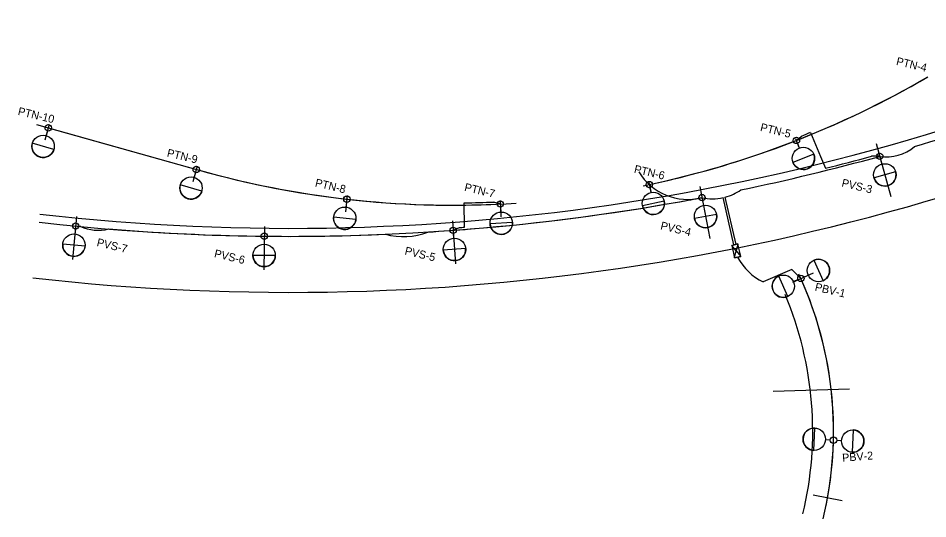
# Model space of a CAD drawing. Extents: x 0 to 511877, y 0 to 6211921.
# Drawn here: x 511512.3 to 511654.3, y 6211732.8 to 6211811 of the extents above; entities that cross this region are included whole.
import ezdxf

# ---------------------------------------------------------------- set-up
doc = ezdxf.new("R2010")
doc.units = 0
for name, color, linetype in [('Help', 7, 'Continuous'), ('TV_U_LYS_Ledn-', 7, 'Continuous'), ('TV_U_LYS_Ledn-ror', 7, 'Continuous'), ('TV_U_LYS_Mastenummer', 7, 'Continuous'), ('TV_U_LYS_Nyx330-Boligvej', 7, 'Continuous'), ('TV_U_LYS_Nyx330-Stamvej', 7, 'Continuous'), ('TV_U_LYS_Nyx330-Trafiksti', 7, 'Continuous'), ('TV_U_LYS_Skab-', 7, 'Continuous')]:
    doc.layers.add(name, color=color, linetype=linetype)

msp = doc.modelspace()

# ---------------------------------------------------------------- linework, layer by layer
at = {"layer": 'Help'}
for p, q in [((511515.14, 6211794.42), (511540.35, 6211787.33)), ((511517.13, 6211794.44), (511516.43, 6211791.98)), ((511633.67, 6211792.24), (511634.19, 6211790.91)), ((511646.25, 6211791.44), (511648.53, 6211783.19)), ((511540.23, 6211787.94), (511539.54, 6211785.48)), ((511610.76, 6211785.36), (511611.05, 6211783.97)), ((511618.71, 6211784.76), (511620.25, 6211776.62)), ((511563.66, 6211783.32), (511563.37, 6211780.78)), ((511587.53, 6211782.56), (511587.65, 6211780.01)), ((511521.4, 6211780.06), (511520.74, 6211773.34)), ((511550.72, 6211778.48), (511550.63, 6211771.73)), ((511580.07, 6211779.4), (511580.56, 6211772.67)), ((511633.21, 6211769.81), (511636.48, 6211771.28)), ((511630.16, 6211752.75), (511642.1, 6211753.13)), ((511636.43, 6211736.57), (511640.94, 6211735.7))]:
    msp.add_line(p, q, dxfattribs=at)
for centre, radius, start, end in [((511554.61, 6212123.21), 345, 263.5186, 295.1994), ((511554.61, 6212123.21), 355, 263.5186, 295.1994), ((511580.2, 6211928.88), 147.05, 281.6292, 300.2652), ((511580.2, 6211928.88), 147.05, 254.2791, 273.838), ((511616.85, 6211791.73), 9, 211.5009, 283.9445), ((511554.61, 6212123.21), 346.25, 263.5186, 280.7247), ((511581.09, 6211746.49), 58.5, 346.4926, 24.8224), ((511581.09, 6211746.49), 55.25, 346.4926, 22.7418)]:
    msp.add_arc(centre, radius, start, end, dxfattribs=at)
at = {"layer": 'TV_U_LYS_Ledn-'}
for p, q in [((511516.97, 6211793.91), (511540.35, 6211787.33)), ((511633.79, 6211791.94), (511634.58, 6211792.63)), ((511637.56, 6211789.41), (511638.31, 6211787.59)), ((511646.8, 6211789.46), (511645.51, 6211789.47)), ((511587.56, 6211782.01), (511586.57, 6211782.31)), ((511522.04, 6211778.49), (511521.25, 6211778.57)), ((511580.19, 6211777.9), (511581.17, 6211778.33)), ((511634.49, 6211770.39), (511633.07, 6211771.78))]:
    msp.add_line(p, q, dxfattribs=at)
for centre, radius, start, end in [((511554.61, 6212123.21), 346.25, 286.3745, 293.4585), ((511580.2, 6211928.88), 147.05, 282.0219, 300.2652), ((511580.2, 6211928.88), 146.7, 291.7596, 292.3584), ((511647.88, 6211795.97), 6.6, 260.5947, 311.2205), ((511554.61, 6212123.21), 346.25, 281.7491, 285.4407), ((511554.61, 6212123.21), 345.9, 284.003, 285.2354), ((511580.2, 6211928.88), 147.05, 254.2791, 272.8705), ((511620.64, 6211790.79), 7.96, 284.8391, 304.2822), ((511554.61, 6212123.21), 346.25, 280.141, 280.7184), ((511620.64, 6211790.79), 7.96, 258.1853, 282.318), ((511580.2, 6211928.88), 146.7, 270.6777, 272.4915), ((511524.76, 6211784.77), 6.86, 246.1315, 283.7568), ((511554.61, 6212123.21), 346.25, 265.3253, 272.4814), ((511572.39, 6211787.61), 10.7, 254.9213, 291.142), ((511554.61, 6212123.21), 346.25, 273.5819, 274.6823), ((511554.61, 6212123.21), 345.9, 274.4039, 274.5374), ((511632.66, 6211777.97), 9.1, 208.5425, 243.4498), ((511581.09, 6211746.49), 58.5, 346.4926, 24.109)]:
    msp.add_arc(centre, radius, start, end, dxfattribs=at)
at = {"layer": 'TV_U_LYS_Ledn-ror'}
for p, q in [((511636, 6211793.2), (511637.56, 6211789.41)), ((511624.04, 6211775.62), (511622.33, 6211783.01)), ((511624.38, 6211775.7), (511622.67, 6211783.1)), ((511581.98, 6211778.39), (511581.93, 6211782.19)), ((511633.07, 6211771.78), (511628.6, 6211769.83))]:
    msp.add_line(p, q, dxfattribs=at)
msp.add_arc((511554.61, 6212123.21), 346.25, 274.6823, 280.141, dxfattribs=at)
at = {"layer": 'TV_U_LYS_Nyx330-Boligvej'}
for p, q in [((511636.52, 6211773.22), (511637.95, 6211770.02)), ((511636.52, 6211773.22), (511636.52, 6211773.22)), ((511632.46, 6211767.56), (511631.03, 6211770.76)), ((511634.03, 6211770.18), (511633.35, 6211769.88)), ((511634.95, 6211770.59), (511635.63, 6211770.9)), ((511632.46, 6211767.56), (511632.46, 6211767.56)), ((511636.5, 6211743.51), (511636.66, 6211747.01)), ((511642.66, 6211746.73), (511642.5, 6211743.23)), ((511642.66, 6211746.73), (511642.66, 6211746.73)), ((511639.08, 6211745.14), (511638.33, 6211745.18)), ((511640.08, 6211745.1), (511640.83, 6211745.06)), ((511636.5, 6211743.51), (511636.5, 6211743.51))]:
    msp.add_line(p, q, dxfattribs=at)
for centre, radius in [((511637.23, 6211771.62), 1.75), ((511631.75, 6211769.16), 1.75), ((511634.49, 6211770.39), 0.5), ((511634.49, 6211770.39), 0.5), ((511636.58, 6211745.26), 1.75), ((511642.58, 6211744.98), 1.75), ((511639.58, 6211745.12), 0.5), ((511639.58, 6211745.12), 0.5)]:
    msp.add_circle(centre, radius, dxfattribs=at)
for centre, start, end in [((511637.23, 6211771.62), 294.122, 114.052), ((511631.75, 6211769.16), 114.122, 294.052), ((511636.58, 6211745.26), 87.3548, 267.2849), ((511642.58, 6211744.98), 267.3548, 87.2849)]:
    msp.add_arc(centre, 1.75, start, end, dxfattribs=at)
at = {"layer": 'TV_U_LYS_Nyx330-Stamvej'}
for p, q in [((511646.93, 6211788.97), (511647.13, 6211788.25)), ((511649.29, 6211787.03), (511645.91, 6211786.09)), ((511649.29, 6211787.03), (511649.29, 6211787.03)), ((511619.14, 6211782.51), (511619.28, 6211781.78)), ((511621.33, 6211780.38), (511617.88, 6211779.73)), ((511621.33, 6211780.38), (511621.33, 6211780.38)), ((511521.21, 6211778.07), (511521.14, 6211777.32)), ((511580.21, 6211777.4), (511580.27, 6211776.65)), ((511522.72, 6211775.42), (511519.23, 6211775.74)), ((511550.69, 6211776.48), (511550.69, 6211775.73)), ((511522.72, 6211775.42), (511522.72, 6211775.42)), ((511582.14, 6211775.04), (511578.65, 6211774.78)), ((511582.14, 6211775.04), (511582.14, 6211775.04)), ((511552.42, 6211773.96), (511548.92, 6211773.99)), ((511552.42, 6211773.96), (511552.42, 6211773.96))]:
    msp.add_line(p, q, dxfattribs=at)
for centre, radius in [((511646.8, 6211789.46), 0.5), ((511647.6, 6211786.56), 1.75), ((511619.05, 6211783.01), 0.5), ((511619.61, 6211780.06), 1.75), ((511521.25, 6211778.57), 0.5), ((511520.98, 6211775.58), 1.75), ((511550.7, 6211776.98), 0.5), ((511580.18, 6211777.9), 0.5), ((511550.67, 6211773.98), 1.75), ((511580.4, 6211774.91), 1.75)]:
    msp.add_circle(centre, radius, dxfattribs=at)
for centre, start, end in [((511647.6, 6211786.56), 195.4927, 15.4227), ((511619.61, 6211780.06), 190.7683, 10.6984), ((511520.98, 6211775.58), 174.8079, 354.738), ((511580.4, 6211774.91), 184.2397, 4.1698), ((511550.67, 6211773.98), 179.524, 359.454)]:
    msp.add_arc(centre, 1.75, start, end, dxfattribs=at)
at = {"layer": 'TV_U_LYS_Nyx330-Trafiksti'}
for p, q in [((511516.84, 6211793.42), (511516.63, 6211792.7)), ((511517.85, 6211790.54), (511514.48, 6211791.49)), ((511633.97, 6211791.47), (511634.24, 6211790.77)), ((511517.85, 6211790.54), (511517.85, 6211790.54)), ((511636.51, 6211789.78), (511633.25, 6211788.5)), ((511636.51, 6211789.78), (511636.51, 6211789.78)), ((511539.94, 6211786.92), (511539.74, 6211786.2)), ((511540.94, 6211784.04), (511537.57, 6211784.99)), ((511610.93, 6211784.56), (511611.08, 6211783.83)), ((511540.94, 6211784.04), (511540.94, 6211784.04)), ((511563.54, 6211782.27), (511563.46, 6211781.52)), ((511587.58, 6211781.51), (511587.62, 6211780.76)), ((511613.16, 6211782.48), (511609.74, 6211781.75)), ((511613.16, 6211782.48), (511613.16, 6211782.48)), ((511565, 6211779.58), (511561.52, 6211779.98)), ((511565, 6211779.58), (511565, 6211779.58)), ((511589.46, 6211779.1), (511585.96, 6211778.92)), ((511589.46, 6211779.1), (511589.46, 6211779.1))]:
    msp.add_line(p, q, dxfattribs=at)
for centre, radius in [((511516.97, 6211793.91), 0.5), ((511516.16, 6211791.02), 1.75), ((511633.79, 6211791.94), 0.5), ((511634.88, 6211789.14), 1.75), ((511540.08, 6211787.4), 0.5), ((511539.26, 6211784.51), 1.75), ((511610.82, 6211785.05), 0.5), ((511563.6, 6211782.76), 0.5), ((511611.45, 6211782.11), 1.75), ((511563.26, 6211779.78), 1.75), ((511587.56, 6211782.01), 0.5), ((511587.71, 6211779.01), 1.75)]:
    msp.add_circle(centre, radius, dxfattribs=at)
for centre, start, end in [((511516.16, 6211791.02), 164.292, 344.2221), ((511634.88, 6211789.14), 201.4134, 21.3435), ((511539.26, 6211784.51), 164.211, 344.1411), ((511611.45, 6211782.11), 192.0345, 11.9646), ((511563.26, 6211779.78), 173.5319, 353.462), ((511587.71, 6211779.01), 182.8832, 2.8132)]:
    msp.add_arc(centre, 1.75, start, end, dxfattribs=at)
at = {"layer": 'TV_U_LYS_Skab-'}
for points in [[(511624.66, 6211775.77), (511623.69, 6211775.54), (511624.14, 6211773.59), (511625.11, 6211773.82)], [(511624.66, 6211775.77), (511624.4, 6211774.68), (511623.69, 6211775.54)], [(511624.14, 6211773.59), (511624.4, 6211774.68), (511625.11, 6211773.82)]]:
    msp.add_lwpolyline(points, close=True, dxfattribs=at)

# ---------------------------------------------------------------- texts
at = {"layer": 'TV_U_LYS_Mastenummer'}
for s, rotation, p in [('PTN-4', 346.664, (511649.29, 6211803.76)), ('PTN-10', 346.664, (511512.14, 6211795.95)), ('PTN-5', 346.664, (511628.06, 6211793.45)), ('PTN-9', 346.664, (511535.42, 6211789.44)), ('PTN-6', 346.664, (511608.36, 6211786.92)), ('PTN-8', 346.664, (511558.55, 6211784.78)), ('PVS-3', 346.664, (511640.77, 6211784.76)), ('PTN-7', 346.664, (511581.86, 6211784.08)), ('PVS-4', 346.664, (511612.48, 6211778.08)), ('PVS-7', 346.664, (511524.46, 6211775.47)), ('PVS-6', 346.664, (511542.8, 6211773.73)), ('PVS-5', 346.664, (511572.55, 6211774.15)), ('PBV-1', 346.664, (511636.59, 6211768.5)), ('PBV-2', 4.4233, (511640.99, 6211741.74)), ('PBV-2', 4.4233, (511640.99, 6211741.74))]:
    msp.add_text(s, height=1.25, rotation=rotation, dxfattribs=at).set_placement(p)

doc.saveas('drawing.dxf')
